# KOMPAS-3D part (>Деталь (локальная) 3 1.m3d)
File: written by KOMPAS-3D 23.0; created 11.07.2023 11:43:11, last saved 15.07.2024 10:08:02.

Document properties: Автор: Владимир; Полное имя файла: C:\Users\YNA_NN\AppData\Local\Temp\KOMPAS-3D\ktf2-9c35-ef1d-07af\_Деталь (локальная) 3 1.m3d

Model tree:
1. Эскиз:2  (with: Элемент выдавливания:2)
2. Элемент выдавливания:5  (labels: Сталь 3сп ГОСТ 380-2005)
     Расстояние 1 = 10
